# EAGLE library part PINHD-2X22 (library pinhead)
PIN HEADER
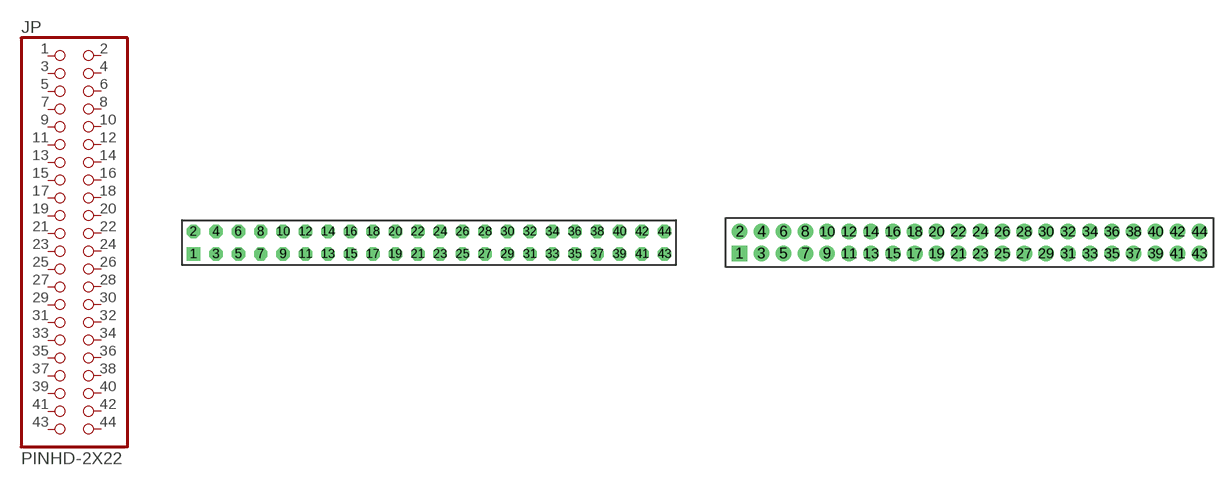
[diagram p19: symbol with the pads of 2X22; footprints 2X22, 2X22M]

Designator prefix JP

## PINHD-2X22  [2X22]
1  1  pas
2  2  pas
3  3  pas
4  4  pas
5  5  pas
6  6  pas
7  7  pas
8  8  pas
9  9  pas
10  10  pas
11  11  pas
12  12  pas
13  13  pas
14  14  pas
15  15  pas
16  16  pas
17  17  pas
18  18  pas
19  19  pas
20  20  pas
21  21  pas
22  22  pas
23  23  pas
24  24  pas
25  25  pas
26  26  pas
27  27  pas
28  28  pas
29  29  pas
30  30  pas
31  31  pas
32  32  pas
33  33  pas
34  34  pas
35  35  pas
36  36  pas
37  37  pas
38  38  pas
39  39  pas
40  40  pas
41  41  pas
42  42  pas
43  43  pas
44  44  pas

## PINHD-2X22M  [2X22M]
Pads as for 2X22

## Footprint 2X22 (pad centres in mm)
PIN HEADER - 0.1"
drill 1.016 square: 1 -25.4,-1.27
drill 1.016 octagon: 2 -25.4,1.27; 3 -22.86,-1.27; 4 -22.86,1.27; 5 -20.32,-1.27; 6 -20.32,1.27; 7 -17.78,-1.27; 8 -17.78,1.27; 9 -15.24,-1.27; 10 -15.24,1.27; 11 -12.7,-1.27; 12 -12.7,1.27; 13 -10.16,-1.27; 14 -10.16,1.27; 15 -7.62,-1.27; 16 -7.62,1.27; 17 -5.08,-1.27; 18 -5.08,1.27; 19 -2.54,-1.27; 20 -2.54,1.27; 21 0,-1.27; 22 0,1.27; 23 2.54,-1.27; 24 2.54,1.27; 25 5.08,-1.27; 26 5.08,1.27; 27 7.62,-1.27; 28 7.62,1.27; 29 10.16,-1.27; 30 10.16,1.27; 31 12.7,-1.27; 32 12.7,1.27; 33 15.24,-1.27; 34 15.24,1.27; 35 17.78,-1.27; 36 17.78,1.27; 37 20.32,-1.27; 38 20.32,1.27; 39 22.86,-1.27; 40 22.86,1.27; 41 25.4,-1.27; 42 25.4,1.27; 43 27.94,-1.27; 44 27.94,1.27

## Footprint 2X22M (pad centres in mm)
PIN HEADER - 2MM"
drill 0.914 square: 1 -21,-1
drill 0.914 round: 2 -21,1; 3 -19,-1; 4 -19,1; 5 -17,-1; 6 -17,1; 7 -15,-1; 8 -15,1; 9 -13,-1; 10 -13,1; 11 -11,-1; 12 -11,1; 13 -9,-1; 14 -9,1; 15 -7,-1; 16 -7,1; 17 -5,-1; 18 -5,1; 19 -3,-1; 20 -3,1; 21 -1,-1; 22 -1,1; 23 1,-1; 24 1,1; 25 3,-1; 26 3,1; 27 5,-1; 28 5,1; 29 7,-1; 30 7,1; 31 9,-1; 32 9,1; 33 11,-1; 34 11,1; 35 13,-1; 36 13,1; 37 15,-1; 38 15,1; 39 17,-1; 40 17,1; 41 19,-1; 42 19,1; 43 21,-1; 44 21,1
